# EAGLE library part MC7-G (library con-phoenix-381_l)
Mini-Combicon 3.81mm horizontal 7-polig (mit Gegenstecker)
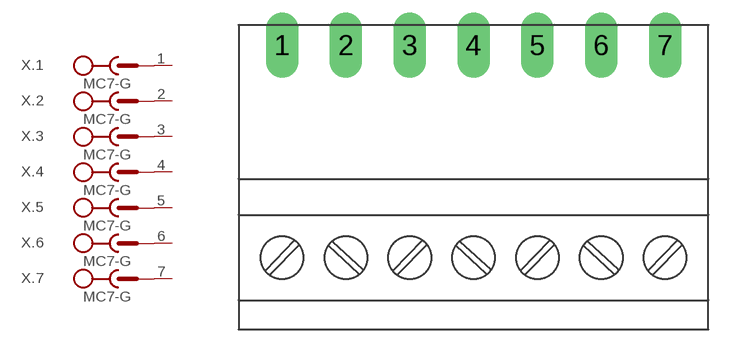
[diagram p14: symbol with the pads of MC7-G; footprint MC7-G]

Designator prefix X; gates .1=SK+V .2=SK+V .3=SK+V .4=SK+V .5=SK+V .6=SK+V .7=SK+V

## MC7-G  [MC7-G]
1  .1:SK  pas
2  .2:SK  pas
3  .3:SK  pas
4  .4:SK  pas
5  .5:SK  pas
6  .6:SK  pas
7  .7:SK  pas

## Footprint MC7-G (pad centres in mm)
Mini-Combicon 3.81mm horizontal 7-polig (mit Gegenstecker)
drill 1.3 long: 1 -11.43,0; 2 -7.62,0; 3 -3.81,0; 4 0,0; 5 3.81,0; 6 7.62,0; 7 11.43,0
